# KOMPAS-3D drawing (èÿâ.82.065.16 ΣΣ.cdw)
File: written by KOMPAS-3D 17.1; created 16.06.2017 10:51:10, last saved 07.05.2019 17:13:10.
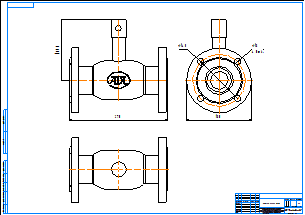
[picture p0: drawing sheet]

Sheet 1: A1, landscape

Title block, sheet 1: name: КШГ.82.065.16 фф; material: Внимание! Данный продукт является объектом авторского права ООО «Торговый Дом АДЛ». / Запрещается изменение, копирование, распространение / (в том числе путем копирования на другие сайты и ресурсы в Интернете) / или любое иное использование информации и объектов без предварительного / согласия правообладателя (ООО «Торговый Дом АДЛ»).; scale: 1:1; sheets: 1; organisation: ООО "Торговый дом АДЛ"; sheet format: A1; stored path: C:\Users\tra\Desktop\2д чертежи\Шаровые краны БИВАЛ\КШ_Бивал_серия_82_85\KOMPAS 2D\КШГ.82.065.16 фф.cdw

Views: Спереди 1, Проекционный вид 2, Проекционный вид 3
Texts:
  Klimkovich
  ADL
Dimensions and other numbers on the sheet: 270; 167,3; 145; 180; 18; 4 Отв.; 1:1; 1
